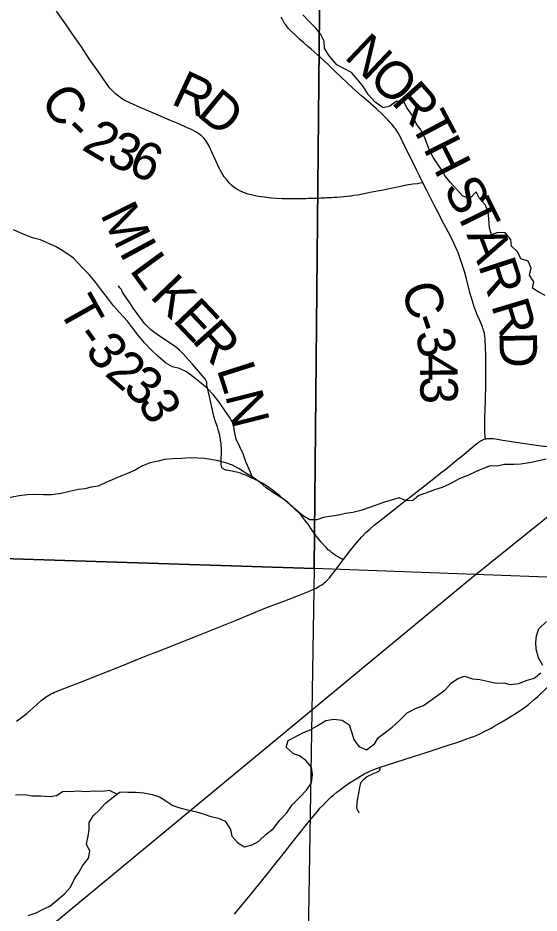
# Model space of a CAD drawing. Extents: x 0 to 34, y 0 to 22.
# Drawn here: x 3.356 to 4.145, y 19.687 to 21.043 of the extents above; entities that cross this region are included whole.
import ezdxf

# ---------------------------------------------------------------- set-up
doc = ezdxf.new("R2010")
doc.units = 0
for name, color, linetype in [('GM_X_Corporation', 7, 'Continuous'), ('GM_X_County_Road', 7, 'Continuous'), ('GM_X_County_Road_Text', 7, 'Continuous'), ('GM_X_Minor_River', 7, 'Continuous'), ('GM_X_Rail_Line', 7, 'Continuous'), ('GM_X_State_Route', 7, 'Continuous'), ('GM_X_Township_Road', 7, 'Continuous'), ('GM_X_Township_Road_Text', 7, 'Continuous')]:
    doc.layers.add(name, color=color, linetype=linetype)

msp = doc.modelspace()

# ---------------------------------------------------------------- linework, layer by layer
at = {"layer": 'GM_X_Corporation'}
for points in [[(2.7974, 21.2696), (3.8139, 21.2086), (3.8046, 20.2092), (2.7815, 20.2421)], [(4.8451, 21.1681), (4.8435, 21.134), (4.8202, 20.1712), (3.8046, 20.2092), (3.8139, 21.2086)], [(3.8046, 20.2092), (3.7879, 19.187), (2.7721, 19.2162), (2.7815, 20.2421)]]:
    msp.add_lwpolyline(points, close=True, dxfattribs=at)
at = {"layer": 'GM_X_County_Road'}
for points in [[(3.969, 20.7933), (3.9648, 20.7927), (3.9607, 20.7921), (3.954, 20.7912), (3.9441, 20.7896), (3.9331, 20.7875), (3.9204, 20.7849), (3.9064, 20.782), (3.8918, 20.7791), (3.8706, 20.7749), (3.8645, 20.774), (3.8602, 20.7734), (3.859, 20.7732), (3.8547, 20.7727), (3.8494, 20.7722), (3.8445, 20.7718), (3.8392, 20.7714), (3.8343, 20.7711), (3.8314, 20.7709), (3.829, 20.7708), (3.8248, 20.7706), (3.8236, 20.7705), (3.8208, 20.7704), (3.8191, 20.7703), (3.8173, 20.7702), (3.8144, 20.77), (3.8101, 20.7699), (3.8034, 20.7696), (3.801, 20.7695), (3.7992, 20.7695), (3.7967, 20.7694), (3.7955, 20.7694), (3.7918, 20.7693), (3.7894, 20.7692), (3.7863, 20.7691), (3.7833, 20.7691), (3.7796, 20.769), (3.7754, 20.769), (3.7721, 20.7689), (3.7644, 20.769), (3.756, 20.7693), (3.7476, 20.7698), (3.7391, 20.7704), (3.7293, 20.7716), (3.7202, 20.7729), (3.7111, 20.7746), (3.7046, 20.7763), (3.6976, 20.7786), (3.692, 20.7811), (3.6872, 20.7837), (3.6831, 20.7865), (3.6794, 20.7896), (3.6755, 20.7935), (3.6719, 20.7977), (3.6683, 20.8027), (3.6647, 20.8084), (3.6602, 20.8165), (3.6554, 20.8266), (3.6504, 20.8379), (3.6449, 20.8498), (3.6421, 20.8548), (3.64, 20.8579), (3.6375, 20.8608), (3.6339, 20.8644), (3.6299, 20.8674), (3.6252, 20.8704), (3.6196, 20.8734), (3.6112, 20.8773), (3.5993, 20.8827), (3.5867, 20.888), (3.5576, 20.9006), (3.541, 20.9077), (3.5251, 20.9147), (3.5179, 20.9183), (3.5126, 20.9213), (3.508, 20.9244), (3.5033, 20.9282), (3.4989, 20.9325), (3.4952, 20.9366), (3.4897, 20.944), (3.4776, 20.9614), (3.4639, 20.9814), (3.4518, 20.9994), (3.4418, 21.0136), (3.4276, 21.034), (3.4141, 21.0535)], [(3.969, 20.7933), (3.9637, 20.804), (3.9594, 20.8129), (3.9393, 20.8542), (3.9356, 20.8614), (3.9329, 20.8663), (3.9311, 20.8694), (3.9294, 20.8723), (3.9279, 20.8746), (3.9262, 20.8769), (3.9242, 20.8796), (3.9219, 20.8823), (3.9191, 20.8854), (3.916, 20.8888), (3.9081, 20.8968), (3.899, 20.9053), (3.8863, 20.9163), (3.876, 20.9252), (3.8629, 20.9367), (3.8363, 20.9621), (3.8267, 20.9717), (3.8185, 20.9793), (3.8102, 20.9867), (3.8046, 20.9916), (3.7999, 20.9957), (3.7942, 21.0005), (3.7882, 21.0058), (3.7822, 21.011), (3.776, 21.0168), (3.77, 21.0226), (3.7652, 21.0278), (3.7613, 21.0327), (3.7597, 21.0349), (3.7584, 21.0369), (3.7573, 21.0389), (3.7562, 21.0407), (3.7554, 21.0426), (3.7546, 21.0445)], [(4.0638, 20.4055), (4.0635, 20.4083), (4.0633, 20.4111), (4.0631, 20.4137), (4.0629, 20.4173), (4.0628, 20.4228), (4.0628, 20.4271), (4.0628, 20.4352), (4.0634, 20.4519), (4.0638, 20.4624), (4.0642, 20.49), (4.0643, 20.5079), (4.0644, 20.5253), (4.0643, 20.5346), (4.0641, 20.5415), (4.0638, 20.5471), (4.0635, 20.5527), (4.0633, 20.5581), (4.0631, 20.56), (4.0629, 20.5618), (4.0626, 20.5638), (4.0622, 20.5657), (4.0615, 20.5681), (4.0607, 20.5705), (4.06, 20.5726), (4.0591, 20.5751), (4.0581, 20.5776), (4.0551, 20.5849), (4.0519, 20.5924), (4.0468, 20.6058), (4.044, 20.614), (4.0402, 20.6271), (4.0349, 20.6481), (4.032, 20.6589), (4.0302, 20.665), (4.0281, 20.6714), (4.0261, 20.6774), (4.0241, 20.6832), (4.0224, 20.6877), (4.0207, 20.6919), (4.0166, 20.7011), (4.0106, 20.7134), (4.001, 20.7315), (3.9896, 20.7529), (3.9862, 20.7595), (3.9789, 20.7738), (3.9744, 20.7826), (3.969, 20.7933)], [(3.8484, 20.2226), (3.86, 20.2375), (3.8646, 20.2433), (3.8693, 20.2491), (3.8767, 20.2574), (3.8828, 20.2636), (3.8855, 20.2662), (3.8887, 20.2691), (3.8953, 20.2747), (3.9083, 20.2851), (3.9377, 20.3081), (3.9509, 20.3184), (3.9832, 20.3437), (3.9968, 20.3545), (4.0036, 20.3599), (4.0196, 20.3728), (4.0311, 20.3822), (4.0388, 20.3886), (4.0508, 20.3984), (4.0522, 20.3995), (4.0536, 20.4005), (4.055, 20.4015), (4.0565, 20.4024), (4.0579, 20.4032), (4.0595, 20.404), (4.0608, 20.4045), (4.0621, 20.405), (4.0638, 20.4055)], [(4.0638, 20.4055), (4.0653, 20.4059), (4.0669, 20.4061), (4.0682, 20.4063), (4.0697, 20.4064), (4.0712, 20.4064), (4.0728, 20.4063), (4.0742, 20.4061), (4.0757, 20.406), (4.079, 20.4055), (4.087, 20.4043), (4.1164, 20.3997), (4.1518, 20.3948), (4.1546, 20.3945), (4.1575, 20.3941), (4.1592, 20.3939), (4.1608, 20.3936), (4.1624, 20.3933), (4.1641, 20.3929)], [(3.3538, 19.9782), (3.3609, 19.9832), (3.3697, 19.9903), (3.3837, 20.0026), (3.3911, 20.0092), (3.3945, 20.012), (3.3977, 20.0143), (3.4001, 20.016), (3.4025, 20.0174), (3.4053, 20.019), (3.4085, 20.0206), (3.4112, 20.0219), (3.4141, 20.0231), (3.4227, 20.0266), (3.4373, 20.032), (3.4569, 20.0396), (3.473, 20.0462), (3.4915, 20.0535), (3.5158, 20.063), (3.5314, 20.0693), (3.5527, 20.0778), (3.566, 20.0831), (3.592, 20.0934), (3.6029, 20.0978), (3.6272, 20.1073), (3.6624, 20.1215), (3.6854, 20.1308), (3.713, 20.1421), (3.7314, 20.1495), (3.7598, 20.1605), (3.7806, 20.1686), (3.7957, 20.1744), (3.8006, 20.1764), (3.8049, 20.1784), (3.8074, 20.1796), (3.8099, 20.181), (3.8121, 20.1823), (3.8142, 20.1836), (3.816, 20.1848), (3.8178, 20.1862), (3.8196, 20.1875), (3.8215, 20.1892), (3.8235, 20.1911), (3.8257, 20.1933), (3.828, 20.1959), (3.8303, 20.1985), (3.8352, 20.2049), (3.8409, 20.2123), (3.8484, 20.2226)]]:
    msp.add_lwpolyline(points, dxfattribs=at)
at = {"layer": 'GM_X_Minor_River'}
for points in [[(4.1543, 20.6225), (4.1448, 20.6277), (4.1353, 20.6337), (4.1371, 20.6435), (4.1306, 20.6533), (4.1328, 20.6639), (4.1285, 20.6745), (4.1175, 20.6782), (4.1129, 20.6884), (4.1034, 20.6974), (4.1025, 20.7076), (4.0937, 20.7177), (4.0828, 20.7184), (4.073, 20.7148), (4.0699, 20.725), (4.069, 20.7387), (4.0678, 20.7496), (4.0639, 20.7595), (4.0547, 20.7696), (4.0497, 20.7798), (4.04, 20.7698), (4.0294, 20.7731), (4.0198, 20.784), (4.0107, 20.7938), (4.0026, 20.8035), (3.9965, 20.8141), (3.985, 20.8314), (3.9796, 20.8415), (3.9754, 20.8517), (3.9715, 20.8623), (3.9657, 20.8736), (3.9589, 20.8834), (3.9527, 20.8958), (3.9454, 20.9064), (3.9397, 20.9173), (3.9287, 20.9164), (3.9189, 20.9095), (3.9088, 20.9071), (3.8966, 20.9153), (3.8863, 20.9273), (3.879, 20.9386), (3.8706, 20.9495), (3.8607, 20.9604), (3.8493, 20.9667), (3.8386, 20.9723), (3.8276, 20.9851), (3.8199, 20.9967), (3.8198, 21.0077), (3.8144, 21.0179), (3.8071, 21.0277), (3.7972, 21.037), (3.7873, 21.0479)], [(3.7111, 20.3477), (3.7048, 20.3617), (3.7006, 20.3726), (3.6971, 20.3828), (3.6917, 20.3937), (3.6863, 20.4054), (3.6836, 20.4168), (3.6823, 20.4277), (3.6762, 20.4383), (3.6682, 20.4503), (3.6605, 20.4612), (3.6517, 20.4721), (3.6426, 20.4822), (3.6315, 20.4916), (3.6212, 20.4994), (3.611, 20.5069), (3.6007, 20.5121), (3.5901, 20.5147), (3.5791, 20.5206), (3.5673, 20.5315), (3.5574, 20.5405), (3.5475, 20.551), (3.5375, 20.5634), (3.5291, 20.5739), (3.5218, 20.5837), (3.5096, 20.5968), (3.5005, 20.6073), (3.4913, 20.6193), (3.4825, 20.6306), (3.4733, 20.643), (3.4634, 20.6546), (3.4535, 20.6644), (3.4397, 20.6794), (3.4253, 20.6895), (3.4135, 20.6966), (3.4036, 20.701), (3.39, 20.7069), (3.3778, 20.7102), (3.3638, 20.7157), (3.349, 20.722)], [(4.1557, 20.3747), (4.1448, 20.3723), (4.1331, 20.3699), (4.1172, 20.3675), (4.1066, 20.367), (4.0926, 20.3669), (4.0813, 20.3645), (4.0711, 20.3647), (4.0594, 20.3601), (4.0485, 20.3558), (4.038, 20.3508), (4.024, 20.3449), (4.0094, 20.3368), (3.9981, 20.3322), (3.9868, 20.3286), (3.9736, 20.3232), (3.963, 20.3197), (3.9533, 20.3116), (3.9427, 20.3123), (3.9332, 20.3163), (3.9211, 20.3128), (3.9109, 20.3096), (3.8883, 20.3018), (3.8751, 20.2971), (3.8631, 20.294), (3.8517, 20.2924), (3.8412, 20.29), (3.831, 20.2887), (3.8185, 20.2863), (3.8083, 20.2832), (3.7978, 20.2831), (3.7867, 20.2894), (3.7753, 20.2999), (3.7643, 20.3096), (3.7525, 20.3178), (3.7426, 20.3238), (3.7319, 20.3313), (3.7224, 20.3395), (3.7118, 20.3473), (3.7011, 20.3537), (3.6909, 20.36), (3.6806, 20.366), (3.6708, 20.3693), (3.659, 20.3725), (3.648, 20.3743), (3.6382, 20.3757), (3.6284, 20.3764), (3.6151, 20.377), (3.6042, 20.3761), (3.5902, 20.3756), (3.5777, 20.3743), (3.5679, 20.372), (3.5558, 20.3692), (3.5445, 20.3649), (3.5332, 20.3583), (3.5216, 20.3533), (3.5118, 20.349), (3.502, 20.3451), (3.4888, 20.3397), (3.4775, 20.3339), (3.4669, 20.3326), (3.4571, 20.3299), (3.4473, 20.329), (3.4337, 20.3259), (3.4213, 20.3231), (3.4066, 20.321), (3.3945, 20.3209), (3.3827, 20.3215), (3.3703, 20.321), (3.3574, 20.3194), (3.3337, 20.315)], [(4.1505, 20.0625), (4.144, 20.0742), (4.1404, 20.087), (4.14, 20.0976), (4.141, 20.1071), (4.1447, 20.1177), (4.1563, 20.1289)], [(3.8836, 19.9347), (3.896, 19.9439), (3.9019, 19.9534), (3.9117, 19.9611), (3.9226, 19.9692), (3.9331, 19.9788), (3.9451, 19.9906), (3.9579, 19.9972), (3.9699, 20.0019), (3.9805, 20.0092), (3.9914, 20.0169), (4.0026, 20.0257), (4.0124, 20.0364), (4.0221, 20.0426), (4.0323, 20.0461), (4.0441, 20.042), (4.0554, 20.041), (4.069, 20.0381), (4.08, 20.0356), (4.0914, 20.0361), (4.1012, 20.0336), (4.1144, 20.0352), (4.1254, 20.0399), (4.1374, 20.043), (4.1476, 20.0515)], [(3.3713, 19.6838), (3.3833, 19.6877), (3.3931, 19.6931), (3.404, 19.6978), (3.4157, 19.7074), (3.4269, 19.7173), (3.4352, 19.7269), (3.4415, 19.7391), (3.4482, 19.749), (3.4538, 19.7589), (3.4624, 19.7704), (3.4646, 19.781), (3.4596, 19.7919), (3.4621, 19.8041), (3.4635, 19.814), (3.4638, 19.8246), (3.4698, 19.8345), (3.4795, 19.8437), (3.4881, 19.8532), (3.5005, 19.8636), (3.5106, 19.8713), (3.5224, 19.8706), (3.5348, 19.8708), (3.5466, 19.8694), (3.5591, 19.8672), (3.5701, 19.8636), (3.58, 19.8572), (3.5902, 19.8505), (3.6008, 19.8468), (3.613, 19.8436), (3.6262, 19.841), (3.638, 19.8374), (3.6478, 19.8337), (3.6596, 19.8312), (3.6694, 19.8267), (3.6775, 19.8139), (3.6798, 19.8037), (3.689, 19.7936), (3.6989, 19.7876), (3.7106, 19.7908), (3.7207, 19.7966), (3.7316, 19.8069), (3.7421, 19.815), (3.7526, 19.828), (3.7623, 19.8387), (3.7709, 19.8516), (3.7825, 19.8631), (3.7926, 19.8738), (3.8005, 19.8849), (3.8019, 19.8974), (3.8003, 19.9084), (3.7919, 19.9185), (3.7824, 19.9256), (3.7729, 19.9286), (3.7622, 19.9387), (3.7648, 19.9486), (3.7764, 19.9551), (3.7873, 19.9606), (3.7983, 19.9652), (3.8092, 19.971), (3.822, 19.9791), (3.8344, 19.9811), (3.8469, 19.9797), (3.8572, 19.9727), (3.8607, 19.9617), (3.8645, 19.9504), (3.8722, 19.9398), (3.8836, 19.9347)], [(3.5057, 19.8675), (3.4944, 19.873), (3.4838, 19.8718), (3.4713, 19.872), (3.4589, 19.8711), (3.446, 19.8721), (3.4358, 19.8709), (3.4241, 19.8715), (3.4143, 19.865), (3.4034, 19.8637), (3.3905, 19.8643), (3.378, 19.8646), (3.3663, 19.8664), (3.3519, 19.8662)]]:
    msp.add_lwpolyline(points, dxfattribs=at)
at = {"layer": 'GM_X_Rail_Line'}
msp.add_lwpolyline([(4.1788, 20.304), (4.0429, 20.1945), (3.3384, 19.6119), (3.2847, 19.5633), (3.2446, 19.5253), (3.2015, 19.4768), (3.1607, 19.4315), (3.1275, 19.3905), (3.0936, 19.3436), (2.5732, 18.599), (2.0707, 17.885), (2.0334, 17.8382), (1.9924, 17.7972), (1.9547, 17.7644), (1.7027, 17.5707), (1.6311, 17.5139)], dxfattribs=at)
at = {"layer": 'GM_X_State_Route'}
msp.add_lwpolyline([(3.684, 19.6857), (3.7075, 19.7146), (3.7334, 19.7462), (3.743, 19.7583), (3.7594, 19.7794), (3.7674, 19.7897), (3.795, 19.8241), (3.8057, 19.837), (3.8093, 19.8415), (3.8131, 19.8461), (3.8178, 19.8511), (3.8221, 19.8556), (3.8264, 19.8599), (3.8303, 19.8634), (3.8342, 19.8667), (3.8388, 19.8704), (3.8444, 19.8747), (3.8508, 19.8796), (3.8581, 19.8846), (3.868, 19.891), (3.8771, 19.8964), (3.881, 19.8987), (3.8846, 19.9006), (3.887, 19.9017), (3.8895, 19.9029), (3.8922, 19.904), (3.895, 19.9051), (3.9042, 19.9084), (3.9154, 19.9119), (3.9546, 19.9244), (3.9742, 19.9307), (4.0073, 19.9416), (4.0206, 19.946), (4.03, 19.9492), (4.0355, 19.9511), (4.0414, 19.9533), (4.0462, 19.955), (4.0506, 19.9568), (4.0542, 19.9584), (4.0585, 19.9605), (4.0631, 19.9628), (4.0683, 19.9655), (4.0725, 19.9677), (4.077, 19.9703), (4.0861, 19.9754), (4.0945, 19.9804), (4.108, 19.9888), (4.1132, 19.9922), (4.1179, 19.9953), (4.1229, 19.9989), (4.1289, 20.0035), (4.1375, 20.0107), (4.1431, 20.0156), (4.1571, 20.0289)], dxfattribs=at)
at = {"layer": 'GM_X_Township_Road'}
for points in [[(3.8484, 20.2226), (3.8464, 20.2237), (3.843, 20.2255), (3.8396, 20.2273), (3.8368, 20.229), (3.834, 20.2309), (3.8313, 20.233), (3.8284, 20.2353), (3.8258, 20.2377), (3.8231, 20.2404), (3.8205, 20.2431), (3.8151, 20.2492), (3.809, 20.257), (3.8021, 20.2665), (3.7952, 20.2762), (3.7903, 20.2826), (3.7856, 20.2884), (3.781, 20.2934), (3.7753, 20.2991), (3.7675, 20.3062), (3.7581, 20.3143), (3.7525, 20.3191), (3.7485, 20.3224), (3.7447, 20.3254), (3.7408, 20.3285), (3.737, 20.3312), (3.7335, 20.3336), (3.7296, 20.3361), (3.7257, 20.3384), (3.7221, 20.3404), (3.7184, 20.3424), (3.7158, 20.3436), (3.7131, 20.345), (3.7101, 20.3463), (3.7071, 20.3477), (3.704, 20.3491), (3.7008, 20.3504), (3.6976, 20.3517), (3.695, 20.3528), (3.6928, 20.3536), (3.6908, 20.3543), (3.6888, 20.3548), (3.6867, 20.3553), (3.6845, 20.3558), (3.6823, 20.3562), (3.6803, 20.3566), (3.6772, 20.357), (3.6741, 20.3576), (3.6722, 20.358), (3.6705, 20.3584), (3.6694, 20.3588), (3.6684, 20.3592), (3.6675, 20.3597), (3.6668, 20.3601), (3.666, 20.3607), (3.6653, 20.3613), (3.6648, 20.3621), (3.6644, 20.3629), (3.6641, 20.3638), (3.6639, 20.3647), (3.6637, 20.3658), (3.6636, 20.3672), (3.6637, 20.3753), (3.6639, 20.384), (3.6639, 20.3927), (3.6638, 20.3951), (3.6636, 20.3976), (3.6627, 20.4044), (3.6614, 20.4111), (3.6597, 20.4177), (3.6578, 20.4236), (3.6552, 20.4312), (3.6536, 20.4366), (3.6526, 20.4402), (3.6503, 20.4492), (3.6482, 20.4582), (3.6458, 20.4698), (3.6443, 20.4764), (3.6433, 20.4807), (3.6425, 20.4843), (3.6421, 20.4876), (3.6417, 20.491), (3.6414, 20.4923), (3.641, 20.4934), (3.6405, 20.4946), (3.6398, 20.4956), (3.639, 20.4968), (3.638, 20.4981), (3.6324, 20.5047), (3.6199, 20.5186), (3.6056, 20.5349), (3.6007, 20.5398), (3.5965, 20.5434), (3.5926, 20.5464), (3.5854, 20.5513), (3.5786, 20.5557), (3.5687, 20.5621), (3.5611, 20.5675), (3.5564, 20.5715), (3.5528, 20.5749), (3.5481, 20.5799), (3.5416, 20.5882), (3.5361, 20.5957), (3.5303, 20.6038), (3.525, 20.6115), (3.5201, 20.6186), (3.518, 20.6216), (3.5158, 20.6253), (3.5143, 20.628), (3.5132, 20.6301), (3.512, 20.6322), (3.5111, 20.6334), (3.5102, 20.6346), (3.5079, 20.6373)], [(3.8727, 19.839), (3.8718, 19.8405), (3.8708, 19.8424), (3.8701, 19.8438), (3.8696, 19.8449), (3.8693, 19.8462), (3.8691, 19.8476), (3.8691, 19.8492), (3.8693, 19.8512), (3.8696, 19.8545), (3.8707, 19.8615), (3.872, 19.8693), (3.8734, 19.8778), (3.874, 19.8804), (3.8745, 19.8822), (3.8748, 19.8833), (3.8753, 19.8844), (3.8758, 19.8855), (3.8765, 19.8866), (3.8772, 19.8877), (3.8781, 19.8887), (3.879, 19.8897), (3.8802, 19.8908), (3.8815, 19.8919), (3.8832, 19.8931), (3.8849, 19.8942), (3.8868, 19.8954), (3.8889, 19.8965), (3.8913, 19.8975), (3.8949, 19.8991), (3.8982, 19.9004), (3.9004, 19.9013), (3.9015, 19.9019), (3.9022, 19.9024), (3.9028, 19.9029), (3.9033, 19.9035), (3.9037, 19.9041), (3.904, 19.9049), (3.9042, 19.9056), (3.9043, 19.9063), (3.9043, 19.907), (3.9042, 19.9084)]]:
    msp.add_lwpolyline(points, dxfattribs=at)

# ---------------------------------------------------------------- texts
at = {"layer": 'GM_X_County_Road_Text'}
for s, rotation, p in [('N', 316.4633, (3.8485, 20.9831)), ('O', 316.4026, (3.8847, 20.9487)), ('R', 334.9903, (3.5859, 20.9137)), ('R', 311.6089, (3.92, 20.9151)), ('C', 303.3534, (3.3883, 20.9194)), ('D', 320.6902, (3.625, 20.896)), ('T', 298.0218, (3.949, 20.8832)), ('-', 315.0444, (3.422, 20.8706)), ('2', 329.229, (3.4506, 20.8447)), ('3', 336.2718, (3.4875, 20.8233)), ('H', 296.8379, (3.9688, 20.8459)), ('6', 336.6674, (3.5199, 20.8091)), ('S', 296.8062, (3.9993, 20.7857)), ('T', 296.3025, (4.0165, 20.7516)), ('A', 290.8767, (4.0348, 20.7148)), ('R', 288.0888, (4.0524, 20.6688)), ('C', 285.3943, (3.9362, 20.6353)), ('R', 286.6981, (4.0722, 20.6081)), ('-', 288.9757, (3.9498, 20.5867)), ('3', 283.2903, (3.957, 20.566)), ('D', 271.2131, (4.0849, 20.5674)), ('4', 270.6297, (3.9646, 20.5352)), ('3', 270.4944, (3.965, 20.5003))]:
    msp.add_text(s, height=0.0568, rotation=rotation, dxfattribs=at).set_placement(p)
at = {"layer": 'GM_X_Township_Road_Text'}
for s, rotation, p in [('M', 296.4416, (3.4798, 20.7457)), ('I', 298.409, (3.5082, 20.6887)), ('L', 306.2023, (3.5237, 20.6611)), ('K', 313.8966, (3.5541, 20.6206)), ('T', 299.3462, (3.4159, 20.6027)), ('E', 313.668, (3.5887, 20.5846)), ('R', 311.6767, (3.6177, 20.5542)), ('-', 305.5239, (3.4403, 20.56)), ('3', 308.6235, (3.4559, 20.5383)), ('2', 318.9899, (3.4855, 20.5029)), ('3', 320.0967, (3.5128, 20.4792)), ('L', 287.6293, (3.6566, 20.5112)), ('3', 298.8754, (3.5362, 20.461)), ('N', 284.1007, (3.6693, 20.4716))]:
    msp.add_text(s, height=0.0568, rotation=rotation, dxfattribs=at).set_placement(p)

doc.saveas('drawing.dxf')
